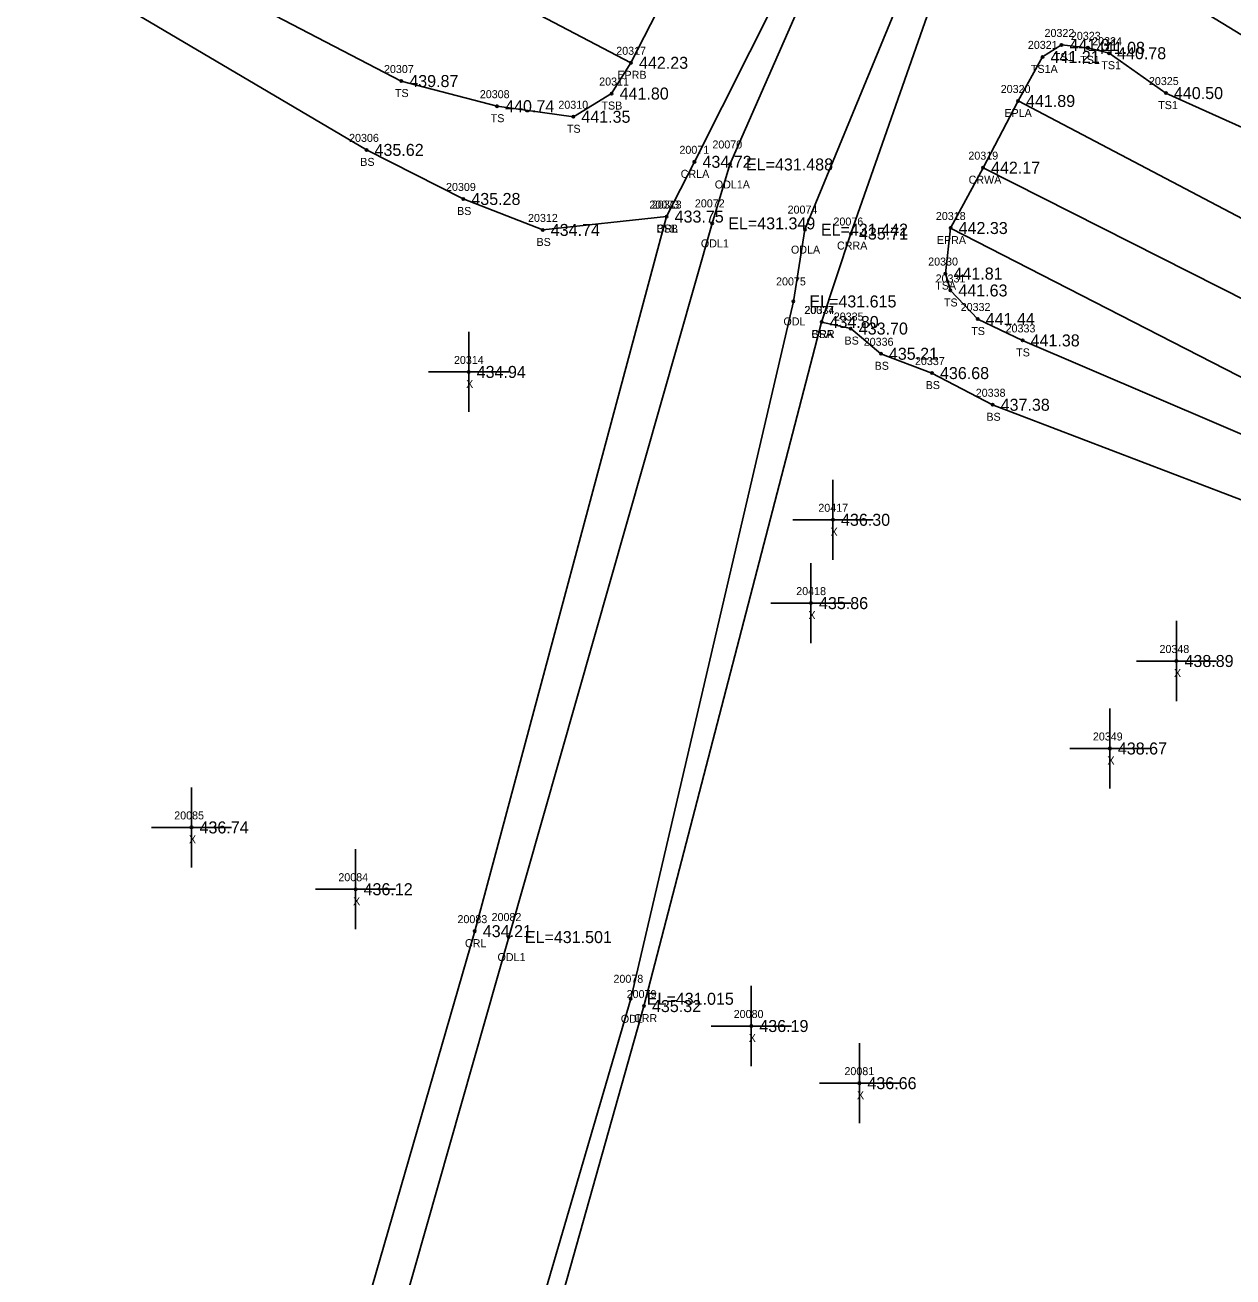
# Model space of a CAD drawing. Extents: x 1810114 to 1811498, y 790790 to 791824.
# Drawn here: x 1810683.9 to 1810834.7, y 791135.9 to 791292.3 of the extents above; entities that cross this region are included whole.
import ezdxf

# ---------------------------------------------------------------- set-up
doc = ezdxf.new("R2010")
doc.units = 0
for name, color, linetype in [('RD_DTM_BkLn1', 7, 'Continuous'), ('RD_DTM_BkLn2', 7, 'Continuous'), ('RD_DTM_BkLn_txCode', 7, 'Continuous'), ('RD_EX_H2O', 7, 'Continuous'), ('RD_EX_H2O_txCode', 7, 'Continuous'), ('RD_EX_Misc', 7, 'Continuous'), ('RD_EX_Misc_txCode', 7, 'Continuous'), ('RD_EX_Road', 7, 'Continuous'), ('RD_EX_Road_txCode', 7, 'Continuous'), ('RD_EX_TX_H2O_ELEV', 7, 'Continuous'), ('RD_EX_TX_Misc_ELEV', 7, 'Continuous'), ('RD_EX_TX_Road_ELEV', 7, 'Continuous'), ('RD_HC_Survey_ELEV', 7, 'Continuous'), ('RD_HC_Survey_txCode', 7, 'Continuous'), ('RD_SMD_Locator', 7, 'Continuous')]:
    doc.layers.add(name, color=color, linetype=linetype)

msp = doc.modelspace()

# ---------------------------------------------------------------- linework, layer by layer
at = {"layer": 'RD_DTM_BkLn1'}
msp.add_lwpolyline([(1810803.51, 791274.51), (1810847.74, 791252.12), (1810893.26, 791230.1), (1810939.59, 791211.03), (1810986.75, 791193.39), (1811034.36, 791179.34), (1811083.17, 791167.31), (1811132.79, 791157.79), (1811182.67, 791151.51), (1811232.87, 791147.29), (1811282.59, 791145.39), (1811332.65, 791144.69), (1811383.13, 791143.44), (1811433.19, 791141.72), (1811483.07, 791139)], dxfattribs=at)
at = {"layer": 'RD_DTM_BkLn2'}
for points in [[(1810136.46, 791613.23), (1810225.09, 791566.55), (1810313.34, 791519.56), (1810402.58, 791471.61), (1810490.03, 791423.34), (1810516.06, 791407.46), (1810541.24, 791393.02), (1810575.56, 791368.65), (1810662.82, 791320.73), (1810730.85, 791285.33), (1810742.82, 791282.19), (1810752.34, 791280.87), (1810757.12, 791283.77)], [(1810135.37, 791610.75), (1810224.14, 791564.21), (1810311.68, 791516.56), (1810401.2, 791468.88), (1810488.81, 791421.27), (1810514.98, 791405.31), (1810539.89, 791390.39), (1810572.74, 791363.8), (1810659.47, 791316.31), (1810726.51, 791276.73), (1810738.6, 791270.6), (1810748.52, 791266.73), (1810763.99, 791268.4)], [(1810770.65, 791309.46), (1810768.4, 791304.34), (1810763.64, 791295.68), (1810759.54, 791287.61), (1810757.12, 791283.77)], [(1810797.71, 791296.87), (1810806.65, 791301.43), (1810818.39, 791301.77), (1810860.19, 791276.21), (1810904.39, 791251.18), (1810946.65, 791228.17), (1810992.83, 791210.21), (1811039.32, 791196), (1811086.62, 791185.05), (1811136.39, 791175.32), (1811184.54, 791168.49), (1811233.77, 791164.27), (1811283.33, 791162.64), (1811288.69, 791162.37)], [(1810810.94, 791288.35), (1810813.31, 791289.84), (1810816.6, 791289.48), (1810819.25, 791288.81), (1810826.35, 791283.83), (1810857.88, 791269.62), (1810901.46, 791245.99), (1810945.33, 791226.23), (1810992.32, 791208.19), (1811038.63, 791193.8), (1811085.97, 791182.59), (1811135.79, 791172.72), (1811184.32, 791165.75), (1811233.45, 791162.61), (1811282.83, 791159.28), (1811288.11, 791158.81), (1811290.26, 791160.7), (1811291.15, 791162.18)], [(1810798.82, 791261.28), (1810799.46, 791266.97), (1810803.51, 791274.51), (1810807.88, 791282.84), (1810810.94, 791288.35)], [(1810798.82, 791261.28), (1810799.43, 791259.17), (1810802.84, 791255.6), (1810808.45, 791252.93), (1810841.34, 791238.85), (1810887.19, 791215.38), (1810933.38, 791195.46), (1810982.02, 791179.58), (1811030.36, 791165.41), (1811080.28, 791153.78), (1811130.64, 791143.41), (1811141.73, 791142.21), (1811149.36, 791140.89), (1811151.79, 791139.84), (1811152.74, 791137.29)], [(1810783.34, 791255.23), (1810786.99, 791254.41), (1810790.75, 791251.26), (1810797.13, 791248.85), (1810804.71, 791244.89), (1810838.03, 791232.12), (1810885, 791211), (1810932.8, 791192.41), (1810981.62, 791176.86), (1811029.91, 791162.73), (1811079.91, 791150.39), (1811130.24, 791140.14), (1811146.59, 791138.06), (1811151.52, 791137.46)]]:
    msp.add_lwpolyline(points, dxfattribs=at)
at = {"layer": 'RD_EX_H2O'}
for p, q in [((1810767.47, 791275.24), (1810781.61, 791303.43)), ((1810783.58, 791301.54), (1810771.9, 791274.91)), ((1810781.26, 791266.77), (1810794.5, 791298.9)), ((1810797.71, 791296.87), (1810787.01, 791266.28))]:
    msp.add_line(p, q, dxfattribs=at)
for points in [[(1810767.47, 791275.24), (1810763.99, 791268.4), (1810740.03, 791179.13), (1810709.69, 791074.11), (1810683.47, 790982.07), (1810621.06, 790917.07), (1810544.86, 790829.8)], [(1810771.9, 791274.91), (1810769.68, 791267.55), (1810744.28, 791178.39), (1810714.79, 791074.77), (1810686.49, 790981.43), (1810623.11, 790914.39), (1810548.58, 790826.46)], [(1810781.26, 791266.77), (1810779.82, 791257.8), (1810759.51, 791170.68), (1810730.33, 791070.87), (1810714.55, 790997.81), (1810711.23, 790989.07), (1810703.16, 790974.66), (1810632.29, 790900.83), (1810555.27, 790820.08)], [(1810787.01, 791266.28), (1810783.34, 791255.23), (1810761.16, 791169.77), (1810733.17, 791070.34), (1810716.3, 790997.73)]]:
    msp.add_lwpolyline(points, dxfattribs=at)
at = {"layer": 'RD_EX_Misc'}
for p, q in [((1810739.27, 791243.99), (1810739.27, 791253.99)), ((1810734.27, 791248.99), (1810744.27, 791248.99)), ((1810784.77, 791225.52), (1810784.77, 791235.52)), ((1810779.77, 791230.52), (1810789.77, 791230.52)), ((1810782.02, 791215.11), (1810782.02, 791225.11)), ((1810777.02, 791220.11), (1810787.02, 791220.11)), ((1810827.67, 791207.88), (1810827.67, 791217.88)), ((1810822.67, 791212.88), (1810832.67, 791212.88)), ((1810819.35, 791196.95), (1810819.35, 791206.95)), ((1810814.35, 791201.95), (1810824.35, 791201.95)), ((1810704.65, 791187.09), (1810704.65, 791197.09)), ((1810699.65, 791192.09), (1810709.65, 791192.09)), ((1810725.14, 791179.37), (1810725.14, 791189.37)), ((1810720.14, 791184.37), (1810730.14, 791184.37)), ((1810774.57, 791162.28), (1810774.57, 791172.28)), ((1810769.57, 791167.28), (1810779.57, 791167.28)), ((1810788.07, 791155.14), (1810788.07, 791165.14)), ((1810783.07, 791160.14), (1810793.07, 791160.14))]:
    msp.add_line(p, q, dxfattribs=at)
at = {"layer": 'RD_EX_Road'}
for points in [[(1810138.18, 791616.8), (1810226.92, 791569.59), (1810315.11, 791521.87), (1810404.37, 791475.11), (1810492.73, 791428.56), (1810580.86, 791380.55), (1810670.21, 791334.43), (1810759.54, 791287.61)], [(1810807.88, 791282.84), (1810852, 791259.68), (1810897.52, 791238.67), (1810942.78, 791219.24), (1810989.92, 791202.01), (1811037.03, 791187.9), (1811084.94, 791176.28), (1811134.78, 791167.28), (1811183.92, 791161.02), (1811232.9, 791156.58), (1811282.68, 791154.92), (1811285.25, 791154.67), (1811313.54, 791153.96), (1811332.83, 791153.68), (1811383.78, 791152.53), (1811433.81, 791151.61), (1811483.97, 791148.18)], [(1810799.46, 791266.97), (1810843.53, 791244.35), (1810889.8, 791222.88), (1810936.32, 791202.72), (1810983.79, 791185.28), (1811031.51, 791170.21), (1811081.62, 791158.02), (1811131.99, 791148.92), (1811148.3, 791146.24), (1811177.02, 791142.75), (1811182.52, 791142.23), (1811232.71, 791137.62), (1811281.86, 791136.25), (1811332.25, 791135.72), (1811383.92, 791134.19), (1811422.24, 791132.82), (1811433.21, 791132.2), (1811452.43, 791131.25), (1811482.29, 791129.59)]]:
    msp.add_lwpolyline(points, dxfattribs=at)
at = {"layer": 'RD_SMD_Locator'}
for centre in [(1810813.31, 791289.84), (1810816.6, 791289.48), (1810810.94, 791288.35), (1810819.25, 791288.81), (1810759.54, 791287.61), (1810730.85, 791285.33), (1810757.12, 791283.77), (1810826.35, 791283.83), (1810742.82, 791282.19), (1810807.88, 791282.84), (1810752.34, 791280.87), (1810726.51, 791276.73), (1810767.47, 791275.24), (1810771.9, 791274.91), (1810803.51, 791274.51), (1810738.6, 791270.6), (1810763.99, 791268.4), (1810763.99, 791268.4), (1810769.68, 791267.55), (1810748.52, 791266.73), (1810781.26, 791266.77), (1810787.01, 791266.28), (1810799.46, 791266.97), (1810798.82, 791261.28), (1810799.43, 791259.17), (1810779.82, 791257.8), (1810783.34, 791255.23), (1810783.34, 791255.23), (1810802.84, 791255.6), (1810786.99, 791254.41), (1810808.45, 791252.93), (1810790.75, 791251.26), (1810739.27, 791248.99), (1810797.13, 791248.85), (1810804.71, 791244.89), (1810784.77, 791230.52), (1810782.02, 791220.11), (1810827.67, 791212.88), (1810819.35, 791201.95), (1810704.65, 791192.09), (1810725.14, 791184.37), (1810740.03, 791179.13), (1810744.28, 791178.39), (1810759.51, 791170.68), (1810761.16, 791169.77), (1810774.57, 791167.28), (1810788.07, 791160.14)]:
    msp.add_circle(centre, 0.15, dxfattribs=at)

# ---------------------------------------------------------------- texts
at = {"layer": 'RD_DTM_BkLn_txCode'}
for s, p in [('20322', (1810811.19, 791290.84)), ('20323', (1810814.48, 791290.48)), ('20321', (1810809.11, 791289.35)), ('20324', (1810817.14, 791289.81)), ('TS1', (1810812.35, 791287.84)), ('TS1', (1810815.64, 791287.48)), ('20307', (1810728.69, 791286.33)), ('TS1A', (1810809.49, 791286.35)), ('TS1', (1810818.29, 791286.81)), ('20311', (1810755.57, 791284.77)), ('20325', (1810824.23, 791284.83)), ('TS', (1810730.06, 791283.33)), ('20308', (1810740.66, 791283.19)), ('20310', (1810750.47, 791281.87)), ('TSB', (1810755.85, 791281.77)), ('TS1', (1810825.39, 791281.83)), ('TS', (1810742.02, 791280.19)), ('20306', (1810724.33, 791277.73)), ('TS', (1810751.54, 791278.87)), ('BS', (1810725.73, 791274.73)), ('20309', (1810736.44, 791271.6)), ('BS', (1810737.82, 791268.6)), ('20313', (1810762.15, 791269.4)), ('20312', (1810746.68, 791267.73)), ('BSB', (1810762.74, 791266.4)), ('BS', (1810747.74, 791264.73)), ('20330', (1810796.66, 791262.28)), ('TSA', (1810797.54, 791259.28)), ('20331', (1810797.59, 791260.17)), ('TS', (1810798.63, 791257.17)), ('20334', (1810781.22, 791256.23)), ('20332', (1810800.72, 791256.6)), ('20335', (1810784.87, 791255.41)), ('BSA', (1810782.07, 791253.23)), ('BS', (1810786.21, 791252.41)), ('TS', (1810802.04, 791253.6)), ('20333', (1810806.33, 791253.93)), ('20336', (1810788.61, 791252.26)), ('TS', (1810807.65, 791250.93)), ('20337', (1810795.01, 791249.85)), ('BS', (1810789.97, 791249.26)), ('BS', (1810796.35, 791246.85)), ('20338', (1810802.6, 791245.89)), ('BS', (1810803.93, 791242.89))]:
    msp.add_text(s, height=1, dxfattribs=at).set_placement(p)
at = {"layer": 'RD_EX_H2O_txCode'}
for s, p in [('20071', (1810765.59, 791276.24)), ('20070', (1810769.71, 791276.91)), ('CRLA', (1810765.75, 791273.24)), ('ODL1A', (1810770.01, 791271.91)), ('20073', (1810761.83, 791269.4)), ('20072', (1810767.52, 791269.55)), ('20074', (1810779.1, 791268.77)), ('20076', (1810784.83, 791267.28)), ('CRL', (1810762.76, 791266.4)), ('ODL1', (1810768.27, 791264.55)), ('ODLA', (1810779.52, 791263.77)), ('CRRA', (1810785.27, 791264.28)), ('20075', (1810777.66, 791259.8)), ('20077', (1810781.18, 791256.23)), ('ODL', (1810778.58, 791254.8)), ('CRR', (1810782.08, 791253.23)), ('20083', (1810737.87, 791180.13)), ('20082', (1810742.13, 791180.39)), ('CRL', (1810738.8, 791177.13)), ('ODL1', (1810742.87, 791175.39)), ('20078', (1810757.35, 791172.68)), ('20079', (1810759, 791170.77)), ('ODL', (1810758.27, 791167.68)), ('CRR', (1810759.91, 791167.77))]:
    msp.add_text(s, height=1, dxfattribs=at).set_placement(p)
at = {"layer": 'RD_EX_Misc_txCode'}
for s, p in [('20314', (1810737.43, 791249.99)), ('X', (1810738.95, 791246.99)), ('20417', (1810782.94, 791231.52)), ('X', (1810784.46, 791228.52)), ('20418', (1810780.18, 791221.11)), ('X', (1810781.7, 791218.11)), ('20348', (1810825.55, 791213.88)), ('X', (1810827.36, 791210.88)), ('20349', (1810817.23, 791202.95)), ('X', (1810819.04, 791199.95)), ('20085', (1810702.49, 791193.09)), ('X', (1810704.33, 791190.09)), ('20084', (1810722.99, 791185.37)), ('X', (1810724.83, 791182.37)), ('20080', (1810772.37, 791168.28)), ('X', (1810774.25, 791165.28)), ('20081', (1810786.2, 791161.14)), ('X', (1810787.76, 791158.14))]:
    msp.add_text(s, height=1, dxfattribs=at).set_placement(p)
at = {"layer": 'RD_EX_Road_txCode'}
for s, p in [('20317', (1810757.7, 791288.61)), ('EPRB', (1810757.84, 791285.61)), ('20320', (1810805.72, 791283.84)), ('EPLA', (1810806.18, 791280.84)), ('20318', (1810797.62, 791267.97)), ('EPRA', (1810797.74, 791264.97))]:
    msp.add_text(s, height=1, dxfattribs=at).set_placement(p)
at = {"layer": 'RD_EX_TX_H2O_ELEV'}
for s, p in [('434.72', (1810768.47, 791274.49)), ('EL=431.488', (1810773.9, 791274.16)), ('433.75', (1810764.99, 791267.65)), ('EL=431.349', (1810771.68, 791266.8)), ('EL=431.442', (1810783.26, 791266.02)), ('435.71', (1810788.01, 791265.53)), ('EL=431.615', (1810781.82, 791257.05)), ('434.80', (1810784.34, 791254.48)), ('434.21', (1810741.03, 791178.38)), ('EL=431.501', (1810746.28, 791177.64)), ('EL=431.015', (1810761.51, 791169.93)), ('435.32', (1810762.16, 791169.02))]:
    msp.add_text(s, height=1.5, dxfattribs=at).set_placement(p)
at = {"layer": 'RD_EX_TX_Misc_ELEV'}
for s, p in [('441.31', (1810814.31, 791289.09)), ('441.08', (1810817.6, 791288.73)), ('440.78', (1810820.25, 791288.06)), ('441.21', (1810811.94, 791287.6)), ('439.87', (1810731.85, 791284.58)), ('441.80', (1810758.12, 791283.02)), ('440.50', (1810827.35, 791283.08)), ('440.74', (1810743.82, 791281.44)), ('441.35', (1810753.34, 791280.12)), ('435.62', (1810727.51, 791275.98)), ('435.28', (1810739.6, 791269.85)), ('433.75', (1810764.99, 791267.65)), ('434.74', (1810749.52, 791265.98)), ('441.81', (1810799.82, 791260.53)), ('441.63', (1810800.43, 791258.42)), ('434.80', (1810784.34, 791254.48)), ('433.70', (1810787.99, 791253.66)), ('441.44', (1810803.84, 791254.85)), ('441.38', (1810809.45, 791252.18)), ('435.21', (1810791.75, 791250.51)), ('434.94', (1810740.27, 791248.24)), ('436.68', (1810798.13, 791248.1)), ('437.38', (1810805.71, 791244.14)), ('436.30', (1810785.77, 791229.77)), ('435.86', (1810783.02, 791219.36)), ('438.89', (1810828.67, 791212.13)), ('438.67', (1810820.35, 791201.2)), ('436.74', (1810705.65, 791191.34)), ('436.12', (1810726.14, 791183.62)), ('436.19', (1810775.57, 791166.53)), ('436.66', (1810789.07, 791159.39))]:
    msp.add_text(s, height=1.5, dxfattribs=at).set_placement(p)
at = {"layer": 'RD_EX_TX_Road_ELEV'}
for s, p in [('442.23', (1810760.54, 791286.86)), ('441.89', (1810808.88, 791282.09)), ('442.33', (1810800.46, 791266.22))]:
    msp.add_text(s, height=1.5, dxfattribs=at).set_placement(p)
at = {"layer": 'RD_HC_Survey_ELEV'}
msp.add_text('442.17', height=1.5, dxfattribs=at).set_placement((1810804.51, 791273.76))
at = {"layer": 'RD_HC_Survey_txCode'}
for s, p in [('20319', (1810801.68, 791275.51)), ('CRWA', (1810801.71, 791272.51))]:
    msp.add_text(s, height=1, dxfattribs=at).set_placement(p)

doc.saveas('drawing.dxf')
